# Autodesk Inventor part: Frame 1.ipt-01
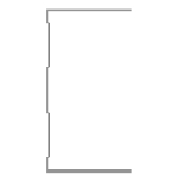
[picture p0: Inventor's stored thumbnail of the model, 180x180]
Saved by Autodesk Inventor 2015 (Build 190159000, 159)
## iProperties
IsCustomPart: 1
_CCFamilyMember: 1
_CCFamilyDisplayName: Kévin - Kévin Novo
_FrameMemberDoc: Frame Member File
_Version: 15.0.0
_GetPNFromCC: 1
Created: 2015-04
Part Number: Frame 1.ipt-01
Material: Aluminum 6061
Description: Kévin Novo
Document SubType Name: Modeling
Standard: Kevin
Designer: suporte
Standards Organization: Kevin
Language: en-US
Size Designation: (Unnamed 1)
Categories: <MemberInstance><Categories><Category DisplayName="Structural Shapes" InternalName="089c4875-fa83-4c05-b084-43b9cc11f5ed" Mnemonic="GRDR"><CategoryParameter Dis
Density: 2.7 g/cm^3
Appearance: Aluminum - Flat
G_L: 2100,000 mm
G_W: 50,000 mm
G_H: 75,000 mm
+D3B04A21-5B23-4792-A896-A304ACCD1228+CUTDETAIL1: Notch
+0647588C-9905-4640-9FAB-B2C768C3238F+CUTDETAIL2: Notch
Author: suporte
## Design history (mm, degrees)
node "Start Plane"
node "End Plane"
sketch "Sketch"
  geometry: L1 (24.7, 37.5)-(24.7, 36.9); L2 (24.7, 36.9)-(-24.7, 36.9); L3 (-24.7, -36.9)-(24.7, -36.9); L4 (24.7, -36.9)-(24.7, -37.5); L5 (24.7, -37.5)-(-25.3, -37.5); L6 (-25.3, 37.5)-(24.7, 37.5); L7 (-24.7, 36.9)-(-24.7, 31.9); L8 (-24.7, 31.9)-(-23.3, 30.5); L9 (-23.3, 30.5)-(-23.3, 10.934); L10 (-23.3, 10.934)-(-24.7, 9.534); L11 (-24.7, 9.534)-(-24.7, -9.534); L12 (-24.7, -9.534)-(-23.3, -10.934); L13 (-23.3, -10.934)-(-23.3, -30.5); L14 (-23.3, -30.5)-(-24.7, -31.9); L15 (-24.7, -31.9)-(-24.7, -36.9); L16 (-25.3, -37.5)-(-25.3, -31.651); L17 (-25.3, -31.651)-(-23.9, -30.251); L18 (-23.9, -30.251)-(-23.9, -11.183); L19 (-23.9, -11.183)-(-25.3, -9.783); L20 (-25.3, -9.783)-(-25.3, 9.783); L21 (-25.3, 9.783)-(-23.9, 11.183); L22 (-23.9, 11.183)-(-23.9, 30.251); L23 (-23.9, 30.251)-(-25.3, 31.651); L24 (-25.3, 31.651)-(-25.3, 37.5); L25 (-25.3, 0)-(30.37, 0); 3 further points
  constraints: 50 end point, 10 point on line, 9 parallel, 5 perpendicular, 4 equal length, 3 midpoint, 3 vertical, 2 vertical alignment, 1 collinear, 1 horizontal, 1 horizontal alignment
  dimensions: "d3" = 0.6 distance of L1.start L1.end (= d6); "d5" = 75 distance between parallel lines of L5 L6; "d6" = 0.6 distance between parallel lines of L24 L7 (= d8); "d7" = 0.6 distance between parallel lines of L8 L23 (= d8); "d8" = 0.6 distance between parallel lines of L22 L9 (= d12); "Espessura" = 0.6 distance between parallel lines of L17 L14; "d10" = 0.6 distance between parallel lines of L13 L18 (= Espessura); "d11" = 0.6 distance between parallel lines of L12 L19 (= Espessura); "d12" = 0.6 distance between parallel lines of L21 L10 (= d11); "d13" = 5 distance of L2.end L7.end; "d15" = 135 deg angle of L9 L8; "d16" = 2 distance between parallel lines of L24 L9; "d17" = 50 distance of L6.start L1.start
extrude "Body" join sketch "Sketch" stored distance "d24" = 0.13; taper "d25" = 0 deg
node "Driven Length"
  sketch "Sketch10"
    geometry: L1 (0, 0)-(10, 0) reference
    constraints: 2 end point, 1 horizontal
  workplane "Work Plane7"
  sketch "Sketch11"
    geometry: L1 (-2, 0)-(12, 0) reference; L2 (-2, 2100)-(12, 2100) reference
    dimensions: "d27" = 2100 distance between parallel lines of L1 L2 (derived)
workplane "Work Plane8"
workplane "Work Plane9"
workplane "Work Plane10"
sketch "Sketch12"
  geometry: L1 (24.7, 37.5)-(24.7, 36.9); L2 (24.7, 36.9)-(-24.7, 36.9); L3 (-24.7, 36.9)-(-24.7, 31.9); L4 (-24.7, 31.9)-(-23.3, 30.5); L5 (-23.3, 30.5)-(-23.3, 10.934); L6 (-23.3, 10.934)-(-24.7, 9.534); L7 (-24.7, 9.534)-(-24.7, -9.534); L8 (-24.7, -9.534)-(-23.3, -10.934); L9 (-23.3, -10.934)-(-23.3, -30.5); L10 (-23.3, -30.5)-(-24.7, -31.9); L11 (-24.7, -31.9)-(-24.7, -36.9); L12 (-24.7, -36.9)-(24.7, -36.9); L13 (24.7, -36.9)-(24.7, -37.5); L14 (24.7, -37.5)-(-25.3, -37.5); L15 (-25.3, -37.5)-(-25.3, -31.651); L16 (-25.3, -31.651)-(-23.9, -30.251); L17 (-23.9, -30.251)-(-23.9, -11.183); L18 (-23.9, -11.183)-(-25.3, -9.783); L19 (-25.3, -9.783)-(-25.3, 9.783); L20 (-25.3, 9.783)-(-23.9, 11.183); L21 (-23.9, 11.183)-(-23.9, 30.251); L22 (-23.9, 30.251)-(-25.3, 31.651); L23 (-25.3, 31.651)-(-25.3, 37.5); L24 (-25.3, 37.5)-(24.7, 37.5)
  constraints: 48 end point, 10 point on line
extrude "Extrusion3" cut sketch "Sketch12" stored distance "d36" = 0.13; taper "d37" = 0 deg
workplane "Work Plane11"
workplane "Work Plane12"
workplane "Work Plane13"
sketch "Sketch13"
  geometry: L1 (24.7, 37.5)-(24.7, 36.9); L2 (24.7, 36.9)-(-24.7, 36.9); L3 (-24.7, 36.9)-(-24.7, 31.9); L4 (-24.7, 31.9)-(-23.3, 30.5); L5 (-23.3, 30.5)-(-23.3, 10.934); L6 (-23.3, 10.934)-(-24.7, 9.534); L7 (-24.7, 9.534)-(-24.7, -9.534); L8 (-24.7, -9.534)-(-23.3, -10.934); L9 (-23.3, -10.934)-(-23.3, -30.5); L10 (-23.3, -30.5)-(-24.7, -31.9); L11 (-24.7, -31.9)-(-24.7, -36.9); L12 (-24.7, -36.9)-(24.7, -36.9); L13 (24.7, -36.9)-(24.7, -37.5); L14 (24.7, -37.5)-(-25.3, -37.5); L15 (-25.3, -37.5)-(-25.3, -31.651); L16 (-25.3, -31.651)-(-23.9, -30.251); L17 (-23.9, -30.251)-(-23.9, -11.183); L18 (-23.9, -11.183)-(-25.3, -9.783); L19 (-25.3, -9.783)-(-25.3, 9.783); L20 (-25.3, 9.783)-(-23.9, 11.183); L21 (-23.9, 11.183)-(-23.9, 30.251); L22 (-23.9, 30.251)-(-25.3, 31.651); L23 (-25.3, 31.651)-(-25.3, 37.5); L24 (-25.3, 37.5)-(24.7, 37.5)
  constraints: 48 end point, 10 point on line
extrude "Extrusion4" cut sketch "Sketch13" stored distance "d38" = 0.13; taper "d39" = 0 deg
body "Solid1"
other parameters: "G_OFFSET_START" = 0 [user parameter; used in 1 equation term], "G_OFFSET_END" = 0 [user parameter; used in 1 equation term], "d22" = 0 (computed from G_OFFSET_START), "G_L" = 2100 (= d27) [user parameter], "d34" = 90 deg
